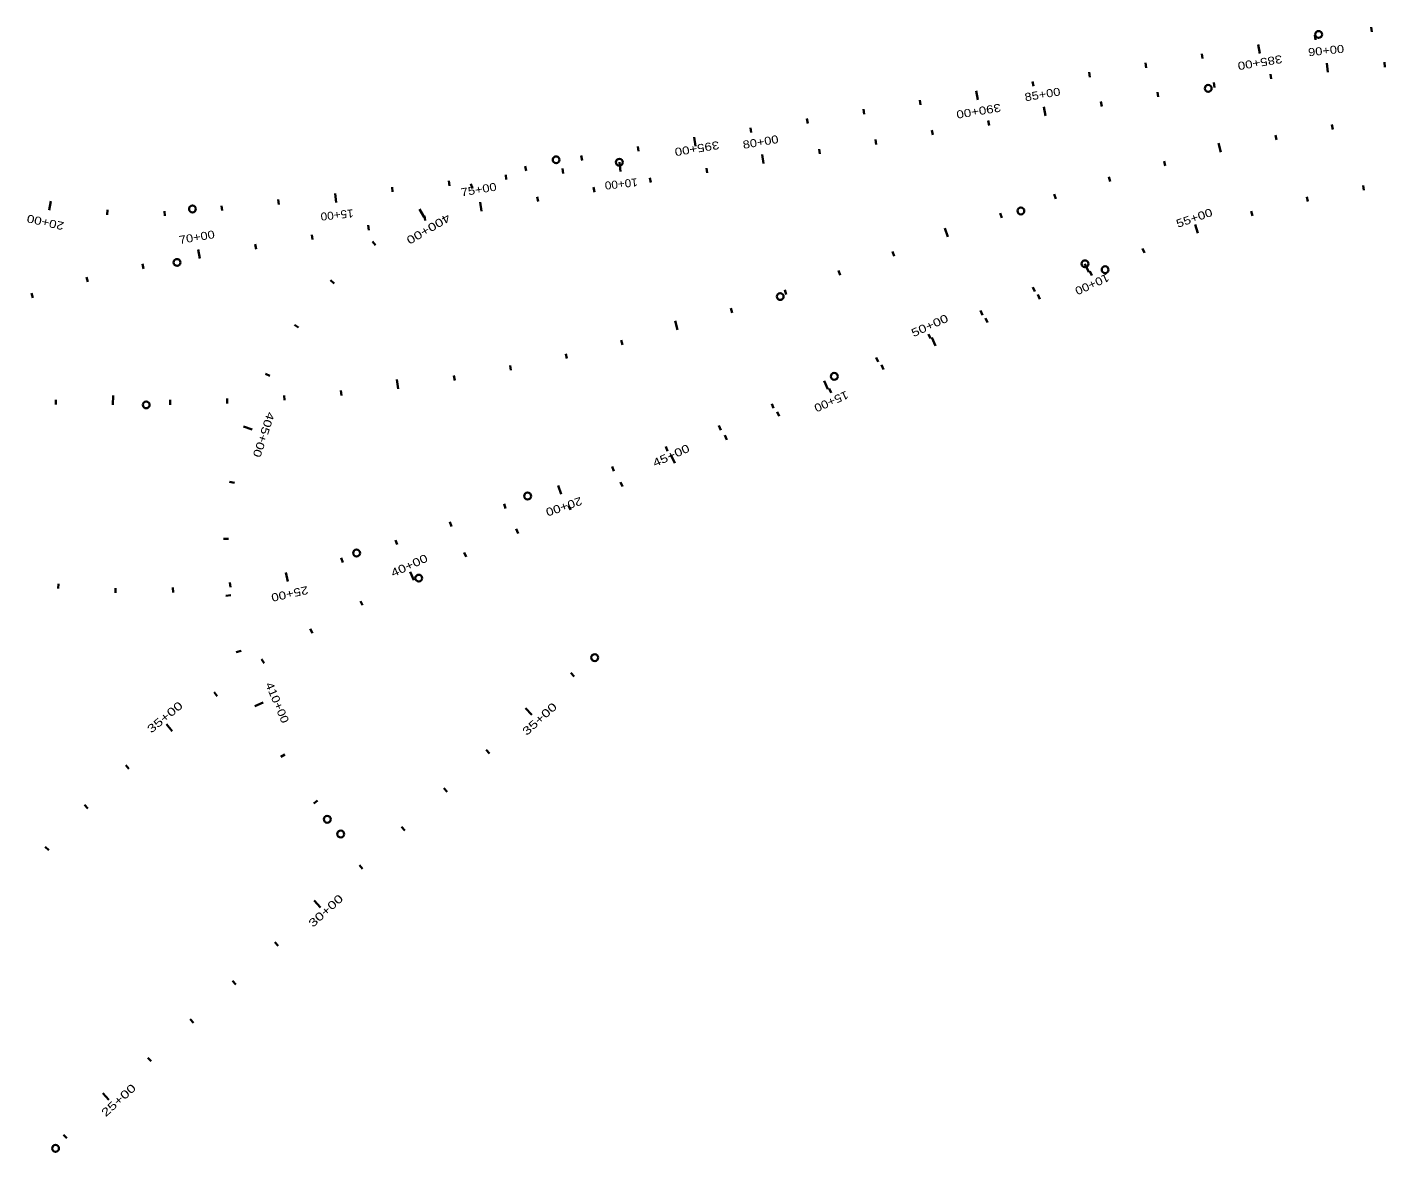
# Model space of a CAD drawing. Extents: x 2357892 to 2370172, y 6966790 to 6985499.
# Drawn here: x 2365397 to 2367771, y 6976683 to 6978650 of the extents above; entities that cross this region are included whole.
import ezdxf
from ezdxf.enums import TextEntityAlignment as Align

# ---------------------------------------------------------------- set-up
doc = ezdxf.new("R2010")
doc.units = 0
doc.header["$LTSCALE"] = 5.6
doc.layers.add('28', color=7, linetype='Continuous', lineweight=35)

msp = doc.modelspace()

# ---------------------------------------------------------------- linework, layer by layer
at = {"layer": '28'}
for p, q in [((2367747.624, 6978650.291), (2367748.592, 6978641.846)), ((2367648.617, 6978636.316), (2367649.995, 6978627.929)), ((2367451.263, 6978603.89), (2367452.641, 6978595.502)), ((2367549.94, 6978620.103), (2367552.534, 6978604.315)), ((2367352.586, 6978587.676), (2367353.964, 6978579.289)), ((2367671.68, 6978571.566), (2367670.04, 6978587.482)), ((2367771.298, 6978580.297), (2367770.686, 6978588.775)), ((2367155.232, 6978555.25), (2367156.61, 6978546.862)), ((2367253.909, 6978571.463), (2367255.287, 6978563.075)), ((2367473.476, 6978545.001), (2367472.09, 6978553.388)), ((2367572.375, 6978559.798), (2367571.246, 6978568.222)), ((2367056.555, 6978539.036), (2367059.149, 6978523.248)), ((2367374.868, 6978528.374), (2367373.453, 6978536.756)), ((2366859.201, 6978506.609), (2366860.58, 6978498.222)), ((2366957.878, 6978522.823), (2366959.257, 6978514.435)), ((2367177.658, 6978495.082), (2367174.995, 6978510.859)), ((2367276.263, 6978511.728), (2367274.848, 6978520.109)), ((2366760.525, 6978490.396), (2366761.903, 6978482.008)), ((2367079.053, 6978478.435), (2367077.638, 6978486.817)), ((2367680.238, 6978471.496), (2367678.804, 6978479.874)), ((2366563.171, 6978457.969), (2366565.765, 6978442.181)), ((2366661.848, 6978474.183), (2366663.226, 6978465.795)), ((2366980.449, 6978461.789), (2366979.034, 6978470.171)), ((2367581.944, 6978453.126), (2367580.255, 6978461.457)), ((2366464.494, 6978441.756), (2366465.872, 6978433.368)), ((2366783.239, 6978428.497), (2366781.824, 6978436.878)), ((2366881.844, 6978445.143), (2366880.429, 6978453.524)), ((2367484.256, 6978431.764), (2367480.6, 6978447.34)), ((2366365.817, 6978425.543), (2366367.195, 6978417.155)), ((2366432.46, 6978413.902), (2366434.197, 6978397.997)), ((2366684.634, 6978411.85), (2366681.971, 6978427.627)), ((2367387.266, 6978407.428), (2367385.072, 6978415.64)), ((2366233.642, 6978392.187), (2366234.565, 6978383.737)), ((2366267.557, 6978407.156), (2366269.6, 6978398.905)), ((2366333.051, 6978403.044), (2366333.974, 6978394.595)), ((2366487.425, 6978378.558), (2366486.01, 6978386.939)), ((2366586.03, 6978395.204), (2366584.615, 6978403.585)), ((2367291.065, 6978380.141), (2367288.621, 6978388.283)), ((2366034.825, 6978370.472), (2366035.748, 6978362.022)), ((2366134.234, 6978381.329), (2366135.156, 6978372.879)), ((2366172.55, 6978376.231), (2366175.755, 6978368.358)), ((2366388.82, 6978361.912), (2366387.405, 6978370.293)), ((2367734.706, 6978365.033), (2367733.237, 6978373.405)), ((2365438.362, 6978345.745), (2365434.918, 6978330.12)), ((2365736.598, 6978337.899), (2365737.521, 6978329.449)), ((2365836.007, 6978348.756), (2365836.93, 6978340.307)), ((2365935.416, 6978359.614), (2365937.153, 6978343.709)), ((2366191.61, 6978328.619), (2366188.947, 6978344.396)), ((2366290.215, 6978345.265), (2366288.8, 6978353.647)), ((2367195.742, 6978349.93), (2367193.051, 6978357.993)), ((2367636.71, 6978345.174), (2367634.804, 6978353.458)), ((2365537.146, 6978330.66), (2365536.415, 6978322.192)), ((2365637.053, 6978328.598), (2365637.434, 6978320.107)), ((2366082.963, 6978331.993), (2366091.061, 6978318.193)), ((2366093.006, 6978311.973), (2366091.591, 6978320.354)), ((2367101.321, 6978317.001), (2367098.471, 6978325.009)), ((2367539.887, 6978320.214), (2367537.55, 6978328.386)), ((2365994.401, 6978295.326), (2365992.986, 6978303.708)), ((2367007.11, 6978283.471), (2367001.745, 6978298.545)), ((2367444.503, 6978290.22), (2367439.305, 6978305.353)), ((2365797.191, 6978262.034), (2365795.776, 6978270.415)), ((2365895.796, 6978278.68), (2365894.381, 6978287.062)), ((2366000.652, 6978275.358), (2366005.961, 6978268.72)), ((2365698.587, 6978245.388), (2365695.923, 6978261.164)), ((2366912.899, 6978249.941), (2366910.049, 6978257.949)), ((2367350.819, 6978255.276), (2367347.641, 6978263.159)), ((2365600.153, 6978227.744), (2365598.455, 6978236.073)), ((2366818.688, 6978216.41), (2366815.838, 6978224.418)), ((2367246.743, 6978236.42), (2367253.301, 6978221.826)), ((2367259.023, 6978215.629), (2367255.54, 6978223.382)), ((2365502.775, 6978204.996), (2365500.607, 6978213.215)), ((2365927.318, 6978207.498), (2365933.525, 6978201.69)), ((2367155.528, 6978195.435), (2367159.012, 6978187.681)), ((2365406.843, 6978176.763), (2365404.213, 6978184.846)), ((2366724.477, 6978182.88), (2366721.627, 6978190.888)), ((2367167.809, 6978174.642), (2367164.325, 6978182.395)), ((2366629.874, 6978150.484), (2366627.242, 6978158.566)), ((2367064.313, 6978154.449), (2367067.796, 6978146.696)), ((2365864.482, 6978129.817), (2365871.458, 6978124.961)), ((2366534.331, 6978120.974), (2366529.844, 6978136.332)), ((2367076.595, 6978133.655), (2367073.111, 6978141.409)), ((2366437.932, 6978094.396), (2366435.798, 6978102.624)), ((2366973.098, 6978113.464), (2366976.581, 6978105.711)), ((2366985.38, 6978092.669), (2366978.822, 6978107.263)), ((2366340.766, 6978070.773), (2366338.885, 6978079.063)), ((2366242.924, 6978050.13), (2366241.297, 6978058.472)), ((2366881.882, 6978072.479), (2366885.366, 6978064.726)), ((2366894.166, 6978051.682), (2366890.682, 6978059.435)), ((2365813.442, 6978043.924), (2365821.042, 6978040.119)), ((2366045.578, 6978017.851), (2366043.479, 6978033.712)), ((2366144.498, 6978032.483), (2366143.125, 6978040.872)), ((2366790.654, 6978031.524), (2366797.162, 6978016.907)), ((2365546.82, 6977989.762), (2365546.874, 6978005.762)), ((2365846.629, 6977997.68), (2365846.03, 6978006.159)), ((2365946.257, 6978006.246), (2365945.4, 6978014.703)), ((2366802.951, 6978010.695), (2366799.467, 6978018.448)), ((2365446.821, 6977990.099), (2365446.85, 6977998.599)), ((2365646.819, 6977989.692), (2365646.739, 6977998.192)), ((2365746.785, 6977992.16), (2365746.446, 6978000.654)), ((2366698.95, 6977991.647), (2366702.271, 6977983.823)), ((2366711.737, 6977969.708), (2366708.253, 6977977.461)), ((2365775.255, 6977951.596), (2365790.442, 6977946.56)), ((2366606.564, 6977953.377), (2366609.748, 6977945.496)), ((2366620.522, 6977928.721), (2366617.038, 6977936.475)), ((2366513.524, 6977916.726), (2366516.57, 6977908.791)), ((2366529.308, 6977887.735), (2366522.75, 6977902.329)), ((2366419.859, 6977881.704), (2366422.766, 6977873.716)), ((2365750.712, 6977854.743), (2365759.08, 6977853.253)), ((2366325.596, 6977848.321), (2366330.806, 6977833.193)), ((2366438.093, 6977846.748), (2366434.609, 6977854.501)), ((2366230.817, 6977816.433), (2366233.505, 6977808.37)), ((2366346.879, 6977805.761), (2366343.395, 6977813.514)), ((2366135.949, 6977784.811), (2366138.637, 6977776.747)), ((2366255.664, 6977764.774), (2366252.18, 6977772.527)), ((2365740.321, 6977755.371), (2365748.816, 6977755.098)), ((2366041.081, 6977753.188), (2366043.769, 6977745.124)), ((2365946.111, 6977721.876), (2365948.611, 6977713.752)), ((2366164.45, 6977723.787), (2366160.966, 6977731.541)), ((2365849.424, 6977696.464), (2365852.846, 6977680.834)), ((2366073.244, 6977682.78), (2366066.616, 6977697.343)), ((2365451.747, 6977676.661), (2365450.763, 6977668.218)), ((2365750.964, 6977679.146), (2365752.088, 6977670.72)), ((2365551.44, 6977669.21), (2365551.158, 6977660.715)), ((2365651.408, 6977670.04), (2365651.831, 6977661.551)), ((2365744.296, 6977655.537), (2365752.743, 6977656.485)), ((2365983.354, 6977638.991), (2365979.433, 6977646.533)), ((2365895.879, 6977590.558), (2365891.568, 6977597.884)), ((2365762.555, 6977557.306), (2365770.779, 6977559.456)), ((2365811.058, 6977537.613), (2365806.37, 6977544.703)), ((2366353.236, 6977514.562), (2366347.514, 6977520.848)), ((2365729.125, 6977480.301), (2365724.072, 6977487.136)), ((2365794.721, 6977462.712), (2365809.46, 6977468.939)), ((2366279.286, 6977447.247), (2366268.515, 6977459.079)), ((2365650.303, 6977418.78), (2365640.132, 6977431.131)), ((2365840.128, 6977373.712), (2365847.402, 6977378.109)), ((2366205.336, 6977379.931), (2366199.614, 6977386.216)), ((2365574.809, 6977353.218), (2365569.07, 6977359.487)), ((2366131.386, 6977312.615), (2366125.664, 6977318.901)), ((2365897.836, 6977292.149), (2365904.403, 6977297.544)), ((2365502.85, 6977283.794), (2365496.791, 6977289.755)), ((2366057.436, 6977245.299), (2366051.715, 6977251.585)), ((2365434.623, 6977210.7), (2365428.26, 6977216.335)), ((2365983.487, 6977177.983), (2365977.765, 6977184.269)), ((2365909.537, 6977110.667), (2365898.766, 6977122.499)), ((2365835.587, 6977043.352), (2365829.865, 6977049.637)), ((2365761.637, 6976976.036), (2365755.915, 6976982.321)), ((2365687.687, 6976908.72), (2365681.965, 6976915.006)), ((2365613.737, 6976841.404), (2365608.016, 6976847.69)), ((2365539.788, 6976774.088), (2365529.017, 6976785.92)), ((2365465.838, 6976706.772), (2365460.116, 6976713.058))]:
    msp.add_line(p, q, dxfattribs=at)
for centre in [(2367655.543, 6978637.455), (2367462.297, 6978543.134), (2366321.854, 6978418.319), (2366432.46, 6978413.902), (2365685.774, 6978332.348), (2367134.664, 6978328.869), (2365658.872, 6978238.683), (2367246.743, 6978236.42), (2367282.107, 6978226.001), (2366713.806, 6978179.082), (2366808.4, 6978039.461), (2365604.963, 6977989.566), (2366271.967, 6977830.15), (2365972.857, 6977730.447), (2366081.625, 6977686.571), (2366389.361, 6977547.447), (2365921.63, 6977264.684), (2365945.176, 6977238.903), (2365446.347, 6976689.03)]:
    msp.add_circle(centre, 6, dxfattribs=at)

# ---------------------------------------------------------------- texts
for s, rotation, width, p in [('385+00', 189.331, 1.25, (2367551.854, 6978595.261)), ('90+00', 5.884, 1.2, (2367669.219, 6978602.477)), ('85+00', 9.582, 1.2, (2367173.664, 6978525.846)), ('390+00', 189.331, 1.25, (2367059.788, 6978510.238)), ('80+00', 9.582, 1.2, (2366680.64, 6978442.615)), ('395+00', 189.331, 1.25, (2366567.126, 6978444.778)), ('10+00', 186.233, 1.1, (2366435.065, 6978383.002)), ('75+00', 9.582, 1.2, (2366187.616, 6978359.383)), ('20+00', 167.568, 1.25, (2365430.18, 6978315.804)), ('15+00', 186.233, 1.1, (2365938.022, 6978328.714)), ('400+00', 210.405, 1.35, (2366095.11, 6978303.178)), ('55+00', 18.956, 1.25, (2367440.28, 6978309.916)), ('70+00', 9.582, 1.2, (2365694.591, 6978276.152)), ('10+00', 204.196, 1.2, (2367256.579, 6978206.854)), ('50+00', 24.197, 1.3, (2366978.097, 6978121.976)), ('15+00', 204.001, 1.2, (2366800.415, 6978001.937)), ('405+00', 251.655, 1.3, (2365803.949, 6977939.636)), ('45+00', 24.197, 1.3, (2366525.86, 6977894.596)), ('20+00', 199.001, 1.25, (2366333.41, 6977818.225)), ('40+00', 24.472, 1.3, (2366067.858, 6977702.303)), ('25+00', 192.351, 1.25, (2365854.557, 6977665.854)), ('410+00', 292.905, 1.2, (2365827.724, 6977466.119)), ('35+00', 39.472, 1.4, (2365642.039, 6977437.883)), ('35+00', 42.311, 1.4, (2366297.6, 6977435.073)), ('30+00', 42.311, 1.4, (2365923.687, 6977099.535)), ('25+00', 42.311, 1.4, (2365561.224, 6976768.165))]:
    msp.add_text(s, height=14, rotation=rotation, dxfattribs=dict(at, width=width)).set_placement(p, align=Align.CENTER)

doc.saveas('drawing.dxf')
